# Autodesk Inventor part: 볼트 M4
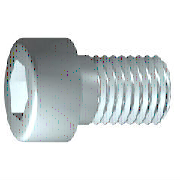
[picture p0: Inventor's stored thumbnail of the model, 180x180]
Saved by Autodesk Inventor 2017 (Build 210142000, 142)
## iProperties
IsCustomPart: 0
Created: 2012-02
Part Number: 볼트 M4
Material: 스테인리스강
Description: 6각 소켓 머리 캡 나사
Document SubType Name: Modeling
Standard: ISO 4762
Designer: mduedu
Standard Revision: Fourth edition 2004-03-01
Standards Organization: ISO
Language: ko-KR
Size Designation: M4 x 10
Categories: <MemberInstance><Categories><Category DisplayName="조임쇠" InternalName="e4da775c-781d-43d5-af7c-5136215cf5a6" Mnemonic="FSTN"><Category DisplayName="볼트" InternalN
Density: 7.75 g/cm^3
Appearance: 반광택
Author: mduedu
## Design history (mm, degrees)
sketch "스케치1"
  geometry: L1 (-1, 0)-(10, 0); L2 (10, 0)-(10, 2); L3 (10, 2)-(1.75, 2); L4 (1.75, 2)-(1.32, 2); L5 (1.32, 2)-(0, 2); L6 (0, 2)-(0, 3.5); L7 (0, 3.5)-(-4, 3.5); L8 (-4, 3.5)-(-4, 1.732); L9 (-4, 1.732)-(-2, 1.732); L10 (-2, 1.732)-(-1, 0); L11 (-6.8, 0)-(12.8, 0) reference; L12 (0, -0.7)-(0, 4.2) reference; L13 (1.75, 2)-(0, 2)
  constraints: 22 end point, 6 parallel, 2 collinear, 2 perpendicular, 1 horizontal, 1 point on line
  dimensions: "d1" = 8.25 distance from line of L3.end L2 (= GEL); "d2" = 0.42952 distance of L4.end L3.end (computed from GAL); "d3" = 4 distance between parallel lines of L8 L6 (= KOH); "d4" = 2 distance of L8.end L9.end (= INTI); "d5" = 60 deg angle of L10 L1; "d6" = 4 diameter of L3 L1 (= GD); "d7" = 4 diameter of L5 L1 (= BDM); "d8" = 3.4641 diameter of L9 L1 (= 1.1547 x SW); "d9" = 7 diameter of L7 L1 (= KOD); "d26" = 10 distance between parallel lines of L12 L2 (= NLG)
revolve "본체" sketch "스케치1" stored, may be unused: angle "d10" = 90 deg
sketch "스케치2"
  geometry: L1 (0, -4.9)-(0, 4.9) reference; L2 (-4.9, 0)-(4.9, 0) reference; L3 (1.732, 0)-(0.866, -1.5); L4 (0.866, -1.5)-(-0.866, -1.5); L5 (-0.866, -1.5)-(-1.732, 0); L6 (-1.732, 0)-(-0.866, 1.5); L7 (-0.866, 1.5)-(0.866, 1.5); L8 (0.866, 1.5)-(1.732, 0); 2 further points
  constraints: 12 end point, 1 coincident, 1 horizontal alignment, 1 point on line, 12 other
extrude "슬롯" join sketch "스케치2" stored distance "d11" = 10; taper "d12" = 0 deg
workplane "Work Plane1"
fillet "Fillet2" dims "d30" = 0.1 (= R)
body "Solid1"
fillet "모깎기1" dims "d17" = 0.4 (= RR)
feature "스레드" dims "d13" = 8.25 (= GEL), "d14" = 0
chamfer "모따기1" distance "d15" = 0.42941 (= -0.5 x SPD + 0.5 x GD); stored, may be unused: second distance "d16" = 0.42941 (= GUL), angle "d27" = 45 deg
other parameters: "GD" = 4 [user parameter; used in 2 equation terms], "NLG" = 10 [user parameter; used in 1 equation term], "GEL" = 8.25 [user parameter; used in 2 equation terms], "KOD" = 7 [user parameter; used in 1 equation term], "KOH" = 4 [user parameter; used in 1 equation term], "INTI" = 2 [user parameter; used in 1 equation term], "GAL" = 0.42941 (= 0.61345 x PTC) [user parameter; used in 1 equation term], "GUL" = 0.42941 (= 0.61345 x PTC) [user parameter; used in 1 equation term], "BDM" = 4 (= NND) [user parameter; used in 1 equation term], "SW" = 3 [user parameter; used in 2 equation terms], "RR" = 0.4 [user parameter; used in 1 equation term], "SPD" = 3.14117 (= NND - 1.2269 x PTC) [user parameter; used in 1 equation term], "d19" = 0, "d28" = 0, "d29" = 0, "R" = 0.1 [user parameter; used in 1 equation term], "TOA" = 30 deg [user parameter], "GD1" = 3.14117 (= THREADDIA - 1.2269 x PTC) [user parameter], "THREADDIA" = 4 [user parameter; used in 1 equation term], "FAWI" = 45 deg [user parameter], "TPU" = 14.28571 (computed from PTC) [user parameter], "PTC" = 0.7 [user parameter; used in 5 equation terms], "NND" = 4 [user parameter; used in 2 equation terms], "E0" = 3.465 (= 1.155 x SW) [user parameter]
